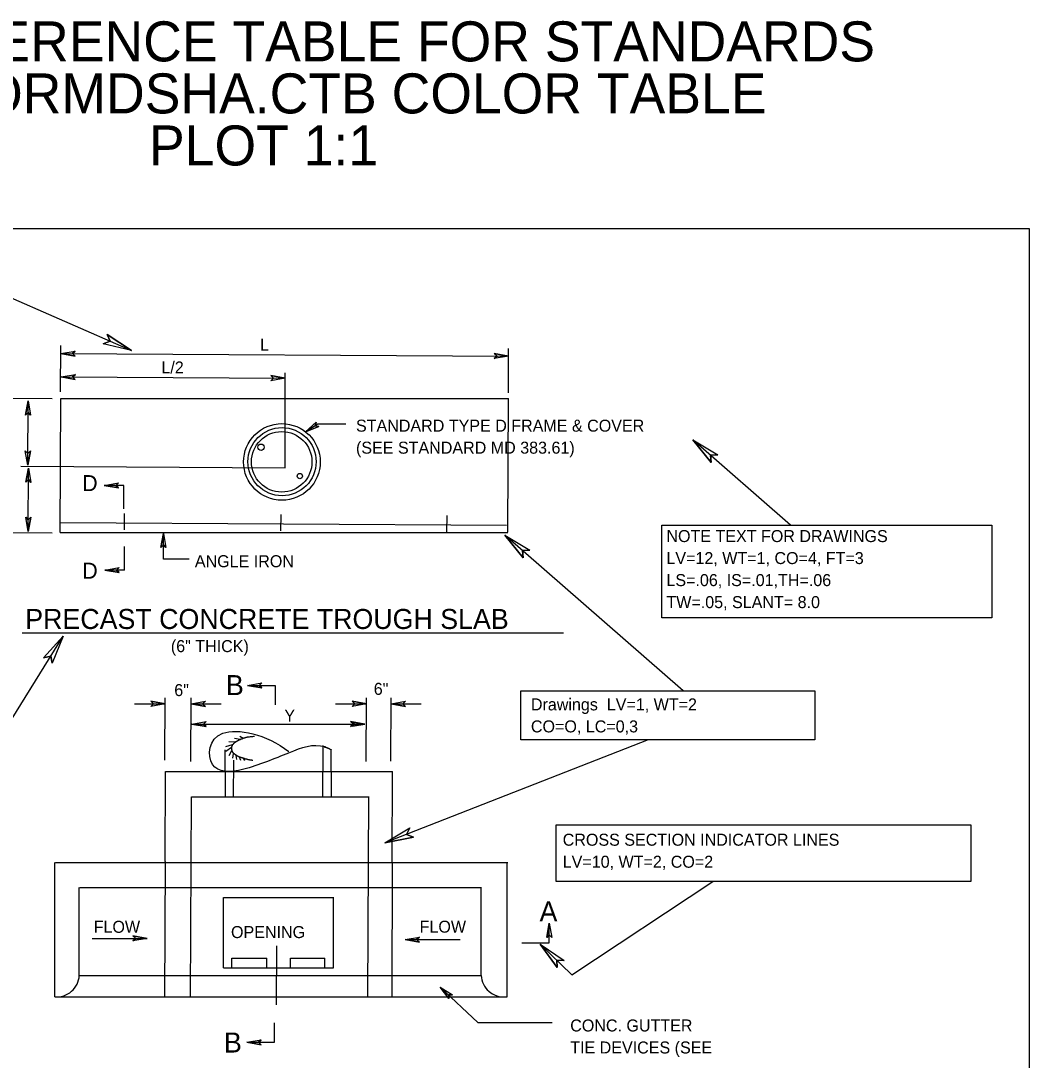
# Model space of a CAD drawing. Extents: x 0 to 1549163, y -476626 to 622136.
# Drawn here: x 2.73 to 7.77, y 12.13 to 17.33 of the extents above; entities that cross this region are included whole.
import ezdxf

# ---------------------------------------------------------------- set-up
doc = ezdxf.new("R2010")
doc.units = 0
for name, color, linetype in [('DETL-DIMS', 7, 'Continuous'), ('DETL-LINE', 7, 'Continuous'), ('DETL-NOTE', 7, 'Continuous'), ('DETL-TITL', 7, 'Continuous'), ('TTLB-TEXT', 7, 'Continuous')]:
    doc.layers.add(name, color=color, linetype=linetype)

msp = doc.modelspace()

# ---------------------------------------------------------------- linework, layer by layer
at = {"layer": 'DETL-DIMS'}
for p, q in [((2.5807, 15.9885), (3.284, 15.6805)), ((3.284, 15.6805), (3.1632, 15.7609)), ((3.1632, 15.7609), (3.1778, 15.7271)), ((2.9303, 15.4751), (2.9317, 15.7053)), ((3.1778, 15.7271), (3.143, 15.7147)), ((3.284, 15.6805), (3.143, 15.7147)), ((5.1671, 15.4696), (5.1684, 15.6913)), ((2.9318, 15.6664), (3.0034, 15.6786)), ((2.9318, 15.6664), (3.0032, 15.6534)), ((2.9318, 15.6664), (5.1682, 15.6528)), ((2.9898, 15.666), (3.0034, 15.6786)), ((3.0032, 15.6534), (2.9898, 15.666)), ((5.1102, 15.6532), (5.0966, 15.6406)), ((5.1682, 15.6528), (5.0966, 15.6406)), ((5.1682, 15.6528), (5.0968, 15.6658)), ((5.0968, 15.6658), (5.1102, 15.6532)), ((2.9324, 15.5491), (3.004, 15.5613)), ((2.9324, 15.5491), (4.0518, 15.5424)), ((2.9324, 15.5491), (3.0038, 15.5361)), ((2.9904, 15.5488), (3.004, 15.5613)), ((3.0038, 15.5361), (2.9904, 15.5488)), ((3.9938, 15.5427), (3.9802, 15.5302)), ((4.0518, 15.5424), (3.9802, 15.5302)), ((4.0518, 15.5424), (3.9804, 15.5554)), ((3.9804, 15.5554), (3.9938, 15.5427)), ((4.0522, 15.0949), (4.0522, 15.5697)), ((2.5551, 15.4426), (2.8876, 15.4406)), ((2.7681, 15.4298), (2.7551, 15.3584)), ((2.7661, 15.108), (2.7681, 15.4298)), ((2.7681, 15.4298), (2.7803, 15.3582)), ((2.7551, 15.3584), (2.7677, 15.3718)), ((2.7677, 15.3718), (2.7803, 15.3582)), ((4.1531, 15.2741), (4.2072, 15.3225)), ((4.2149, 15.3125), (4.1531, 15.2741)), ((4.1531, 15.2741), (4.2205, 15.3011)), ((4.2024, 15.3047), (4.2072, 15.3225)), ((4.2205, 15.3011), (4.2024, 15.3047)), ((4.3543, 15.3125), (4.2149, 15.3125)), ((6.0884, 15.2348), (6.1794, 15.1216)), ((6.0884, 15.2348), (6.2126, 15.1596)), ((6.5764, 14.8078), (6.0884, 15.2348)), ((2.7661, 15.108), (2.7539, 15.1796)), ((2.7665, 15.166), (2.7539, 15.1796)), ((2.7661, 15.108), (2.7791, 15.1794)), ((2.7791, 15.1794), (2.7665, 15.166)), ((6.1758, 15.1584), (6.2126, 15.1596)), ((6.1794, 15.1216), (6.1758, 15.1584)), ((2.7322, 15.103), (4.0522, 15.0949)), ((2.7699, 15.0937), (2.7568, 15.0223)), ((2.7679, 14.7766), (2.7699, 15.0937)), ((2.7699, 15.0937), (2.782, 15.0221)), ((2.7568, 15.0223), (2.7695, 15.0357)), ((2.7695, 15.0357), (2.782, 15.0221)), ((3.1479, 15.0069), (3.2194, 15.0195)), ((3.2059, 15.0069), (3.2194, 15.0195)), ((3.2467, 15.0069), (3.1479, 15.0069)), ((3.1479, 15.0069), (3.2194, 14.9943)), ((3.2194, 14.9943), (3.2059, 15.0069)), ((3.2467, 14.8895), (3.2467, 15.0069)), ((2.7679, 14.7766), (2.7558, 14.8482)), ((2.7683, 14.8346), (2.7558, 14.8482)), ((2.7679, 14.7766), (2.781, 14.848)), ((2.781, 14.848), (2.7683, 14.8346)), ((2.5591, 14.7721), (2.8879, 14.7701)), ((3.4439, 14.7673), (3.4313, 14.6958)), ((3.4439, 14.6375), (3.4439, 14.7673)), ((3.4439, 14.7673), (3.4565, 14.6958)), ((5.15, 14.7583), (5.241, 14.6451)), ((5.15, 14.7583), (5.2742, 14.6831)), ((6.0396, 13.9799), (5.15, 14.7583)), ((3.4313, 14.6958), (3.4439, 14.7093)), ((3.4439, 14.7093), (3.4565, 14.6958)), ((3.2498, 14.5836), (3.2498, 14.7011)), ((5.2374, 14.6819), (5.2742, 14.6831)), ((5.241, 14.6451), (5.2374, 14.6819)), ((3.5721, 14.6375), (3.4439, 14.6375)), ((3.151, 14.5836), (3.2225, 14.5962)), ((3.2498, 14.5836), (3.151, 14.5836)), ((3.151, 14.5836), (3.2225, 14.571)), ((3.209, 14.5836), (3.2225, 14.5962)), ((3.2225, 14.571), (3.209, 14.5836)), ((2.4408, 13.4428), (2.9424, 14.2526)), ((2.9424, 14.2526), (2.8456, 14.1444)), ((2.9424, 14.2526), (2.8886, 14.1178)), ((2.8456, 14.1444), (2.8814, 14.154)), ((2.8814, 14.154), (2.8886, 14.1178)), ((3.8637, 14.0073), (3.9352, 14.0199)), ((3.8637, 14.0073), (4.0018, 14.0073)), ((3.8637, 14.0073), (3.9352, 13.9947)), ((3.9217, 14.0073), (3.9352, 14.0199)), ((3.9352, 13.9947), (3.9217, 14.0073)), ((4.0018, 14.0073), (4.0018, 13.9411)), ((3.4526, 13.9152), (3.3811, 13.9278)), ((3.3811, 13.9278), (3.3946, 13.9152)), ((3.4513, 13.6342), (3.4527, 13.9446)), ((3.5807, 13.6263), (3.582, 13.9446)), ((3.5819, 13.9152), (3.6534, 13.9278)), ((3.6399, 13.9152), (3.6534, 13.9278)), ((4.0018, 13.9411), (4.0018, 13.9099)), ((4.4575, 13.9152), (4.386, 13.9278)), ((4.386, 13.9278), (4.3995, 13.9152)), ((4.4562, 13.6263), (4.4576, 13.9446)), ((4.5798, 13.6292), (4.5812, 13.9446)), ((4.5811, 13.9152), (4.6526, 13.9278)), ((4.6391, 13.9152), (4.6526, 13.9278)), ((3.2991, 13.9152), (3.4526, 13.9152)), ((3.4526, 13.9152), (3.3811, 13.9026)), ((3.3946, 13.9152), (3.3811, 13.9026)), ((3.5819, 13.9152), (3.732, 13.9152)), ((3.5819, 13.9152), (3.6534, 13.9026)), ((3.6534, 13.9026), (3.6399, 13.9152)), ((4.304, 13.9152), (4.4575, 13.9152)), ((4.4575, 13.9152), (4.386, 13.9026)), ((4.3995, 13.9152), (4.386, 13.9026)), ((4.5811, 13.9152), (4.6526, 13.9026)), ((4.5811, 13.9152), (4.7312, 13.9152)), ((4.6526, 13.9026), (4.6391, 13.9152)), ((3.5858, 13.8139), (3.6573, 13.8265)), ((3.6438, 13.8139), (3.6573, 13.8265)), ((4.4506, 13.8139), (4.3791, 13.8265)), ((4.3791, 13.8265), (4.3926, 13.8139)), ((4.3883, 13.8243), (4.4506, 13.8139)), ((4.3883, 13.8243), (4.3961, 13.8139)), ((3.5858, 13.8139), (4.4506, 13.8139)), ((3.5858, 13.8139), (3.6573, 13.8013)), ((3.6573, 13.8013), (3.6438, 13.8139)), ((4.4506, 13.8139), (4.3791, 13.8013)), ((4.3926, 13.8139), (4.3791, 13.8013)), ((4.3883, 13.8035), (4.4506, 13.8139)), ((4.3883, 13.8035), (4.3961, 13.8139)), ((5.8655, 13.7347), (4.5502, 13.2206)), ((4.5502, 13.2206), (4.6742, 13.2962)), ((4.5502, 13.2206), (4.6926, 13.2492)), ((4.6582, 13.2628), (4.6742, 13.2962)), ((4.6926, 13.2492), (4.6582, 13.2628)), ((5.4838, 12.5614), (6.1889, 13.0264)), ((5.3713, 12.8183), (5.3587, 12.7468)), ((5.3713, 12.7208), (5.3713, 12.8183)), ((5.3713, 12.8183), (5.3839, 12.7468)), ((3.0878, 12.7427), (3.3634, 12.7427)), ((3.3634, 12.7427), (3.2919, 12.7553)), ((3.2919, 12.7553), (3.3054, 12.7427)), ((3.3634, 12.7427), (3.2919, 12.7301)), ((3.3054, 12.7427), (3.2919, 12.7301)), ((4.6508, 12.7365), (4.7223, 12.7491)), ((4.6508, 12.7365), (4.9265, 12.7365)), ((4.6508, 12.7365), (4.7223, 12.7239)), ((4.7088, 12.7365), (4.7223, 12.7491)), ((4.7223, 12.7239), (4.7088, 12.7365)), ((5.3587, 12.7468), (5.3713, 12.7603)), ((5.3713, 12.7603), (5.3839, 12.7468)), ((5.2334, 12.7208), (5.3713, 12.7208)), ((5.3256, 12.7141), (5.4838, 12.5614)), ((5.3256, 12.7141), (5.411, 12.5967)), ((5.3256, 12.7141), (5.446, 12.6329)), ((5.411, 12.5967), (5.4091, 12.6335)), ((5.4091, 12.6335), (5.446, 12.6329)), ((5.0149, 12.3232), (4.8264, 12.4999)), ((4.8264, 12.4999), (4.8699, 12.4418)), ((4.8264, 12.4999), (4.8872, 12.4602)), ((4.8699, 12.4418), (4.8687, 12.4602)), ((4.8687, 12.4602), (4.8872, 12.4602)), ((3.9982, 12.2236), (3.9982, 12.3212)), ((5.0149, 12.3232), (5.386, 12.3232)), ((3.8602, 12.2236), (3.9317, 12.2362)), ((3.8602, 12.2236), (3.9982, 12.2236)), ((3.8602, 12.2236), (3.9317, 12.211)), ((3.9182, 12.2236), (3.9317, 12.2362)), ((3.9317, 12.211), (3.9182, 12.2236))]:
    msp.add_line(p, q, dxfattribs=at)
for points in [[(3.1632, 15.7609), (3.284, 15.6805), (3.143, 15.7147), (3.1778, 15.7271)], [(3.0032, 15.6534), (2.9318, 15.6664), (3.0034, 15.6786), (2.9898, 15.666)], [(5.0968, 15.6658), (5.1682, 15.6528), (5.0966, 15.6406), (5.1102, 15.6532)], [(3.0038, 15.5361), (2.9324, 15.5491), (3.004, 15.5613), (2.9904, 15.5488)], [(3.9804, 15.5554), (4.0518, 15.5424), (3.9802, 15.5302), (3.9938, 15.5427)], [(2.7551, 15.3584), (2.7681, 15.4298), (2.7803, 15.3582), (2.7677, 15.3718)], [(4.2205, 15.3011), (4.1531, 15.2741), (4.2072, 15.3225), (4.2024, 15.3047)], [(6.1794, 15.1216), (6.0884, 15.2348), (6.2126, 15.1596), (6.1758, 15.1584)], [(2.7791, 15.1794), (2.7661, 15.108), (2.7539, 15.1796), (2.7665, 15.166)], [(2.7568, 15.0223), (2.7699, 15.0937), (2.782, 15.0221), (2.7695, 15.0357)], [(3.2194, 14.9943), (3.1479, 15.0069), (3.2194, 15.0195), (3.2059, 15.0069)], [(2.781, 14.848), (2.7679, 14.7766), (2.7558, 14.8482), (2.7683, 14.8346)], [(3.4313, 14.6958), (3.4439, 14.7673), (3.4565, 14.6958), (3.4439, 14.7093)], [(5.241, 14.6451), (5.15, 14.7583), (5.2742, 14.6831), (5.2374, 14.6819)], [(3.2225, 14.571), (3.151, 14.5836), (3.2225, 14.5962), (3.209, 14.5836)], [(2.8456, 14.1444), (2.9424, 14.2526), (2.8886, 14.1178), (2.8814, 14.154)], [(3.9352, 13.9947), (3.8637, 14.0073), (3.9352, 14.0199), (3.9217, 14.0073)], [(3.3811, 13.9278), (3.4526, 13.9152), (3.3811, 13.9026), (3.3946, 13.9152)], [(3.6534, 13.9026), (3.5819, 13.9152), (3.6534, 13.9278), (3.6399, 13.9152)], [(4.386, 13.9278), (4.4575, 13.9152), (4.386, 13.9026), (4.3995, 13.9152)], [(4.6526, 13.9026), (4.5811, 13.9152), (4.6526, 13.9278), (4.6391, 13.9152)], [(3.6573, 13.8013), (3.5858, 13.8139), (3.6573, 13.8265), (3.6438, 13.8139)], [(4.3791, 13.8265), (4.4506, 13.8139), (4.3791, 13.8013), (4.3926, 13.8139)], [(5.4056, 13.3099), (7.4777, 13.3099), (7.4777, 13.0264), (5.4056, 13.0264)], [(4.6926, 13.2492), (4.5502, 13.2206), (4.6742, 13.2962), (4.6582, 13.2628)], [(5.3587, 12.7468), (5.3713, 12.8183), (5.3839, 12.7468), (5.3713, 12.7603)], [(3.2919, 12.7553), (3.3634, 12.7427), (3.2919, 12.7301), (3.3054, 12.7427)], [(4.7223, 12.7239), (4.6508, 12.7365), (4.7223, 12.7491), (4.7088, 12.7365)], [(5.411, 12.5967), (5.3256, 12.7141), (5.446, 12.6329), (5.4091, 12.6335)], [(4.8699, 12.4418), (4.8264, 12.4999), (4.8872, 12.4602), (4.8687, 12.4602)], [(3.9317, 12.211), (3.8602, 12.2236), (3.9317, 12.2362), (3.9182, 12.2236)]]:
    msp.add_lwpolyline(points, close=True, dxfattribs=at)
at = {"layer": 'DETL-LINE'}
for p, q in [((2.928, 14.7716), (2.932, 15.4408)), ((2.932, 15.4408), (5.1683, 15.4408)), ((5.1643, 14.7737), (5.1683, 15.4408)), ((3.2489, 14.7849), (3.2494, 14.867)), ((4.0308, 14.7801), (4.0313, 14.8622)), ((2.9297, 14.8212), (5.1569, 14.8077)), ((4.8602, 14.775), (4.8607, 14.8571)), ((2.928, 14.7716), (5.1643, 14.7716)), ((3.8032, 13.7234), (3.7711, 13.7258)), ((3.8275, 13.7363), (3.7995, 13.7426)), ((3.843, 13.7426), (3.8256, 13.7513)), ((3.7523, 13.5744), (3.7527, 13.6857)), ((3.7878, 13.7097), (3.7543, 13.6998)), ((3.7834, 13.6961), (3.7555, 13.6762)), ((3.7847, 13.6806), (3.7711, 13.6551)), ((3.7921, 13.6663), (3.7884, 13.644)), ((4.2409, 13.4477), (4.2419, 13.7062)), ((4.2818, 13.5734), (4.2823, 13.6841)), ((3.7942, 13.4497), (3.795, 13.6336)), ((3.8052, 13.6576), (3.8089, 13.6371)), ((3.8218, 13.6502), (3.8293, 13.6334)), ((3.8398, 13.6445), (3.8485, 13.6315)), ((3.4522, 13.1271), (3.454, 13.577)), ((3.454, 13.577), (4.5889, 13.577)), ((3.7523, 13.5744), (3.7523, 13.4517)), ((4.2818, 13.5734), (4.2812, 13.4497)), ((4.5869, 13.1236), (4.5889, 13.577)), ((3.5789, 12.4513), (3.5833, 13.4502)), ((3.5833, 13.4502), (4.4691, 13.4502)), ((4.4649, 12.4538), (4.4691, 13.4521)), ((2.9011, 12.4507), (2.9011, 13.1228)), ((2.904, 13.1228), (5.1643, 13.1228)), ((3.4522, 13.1271), (3.4492, 12.4507)), ((4.5869, 13.1236), (4.584, 12.4519)), ((5.1613, 12.4507), (5.1613, 13.1228)), ((3.0238, 12.5573), (3.0238, 12.9964)), ((3.0257, 12.9964), (5.0326, 12.9964)), ((5.0306, 12.5573), (5.0306, 12.9964)), ((3.7432, 12.5961), (3.7432, 12.9478)), ((3.7448, 12.9478), (4.2957, 12.9478)), ((4.2942, 12.5961), (4.2942, 12.9478)), ((4.0086, 12.4107), (4.0099, 12.7063)), ((3.7851, 12.5961), (3.7853, 12.6437)), ((3.7853, 12.6437), (3.9609, 12.6437)), ((3.9606, 12.5961), (3.9609, 12.6437)), ((4.0791, 12.5961), (4.0793, 12.6437)), ((4.0793, 12.6437), (4.2498, 12.6437)), ((4.2496, 12.5961), (4.2498, 12.6437)), ((3.7432, 12.5961), (4.2942, 12.5961)), ((3.0238, 12.5573), (5.0306, 12.5573)), ((2.9011, 12.4507), (5.1613, 12.4507))]:
    msp.add_line(p, q, dxfattribs=at)
msp.add_lwpolyline([(5.2291, 13.9799), (6.6982, 13.9799), (6.6982, 13.7347), (5.2291, 13.7347)], close=True, dxfattribs=at)
for centre, major_axis in [((4.0358, 15.1241), (0.1914, 0)), ((4.0364, 15.1254), (0.1702, 0)), ((4.0349, 15.1247), (0.1511, 0)), ((3.9314, 15.1978), (0.0159, 0)), ((4.1254, 15.0535), (0.0134, 0))]:
    msp.add_ellipse(centre, major_axis=major_axis, ratio=0.999935, dxfattribs=at)
for centre, major_axis, start_param, end_param in [((2.9101, 12.5643), (0.1139, 0), 4.632879, 6.222037), ((5.1444, 12.5643), (-0.1139, 0), 0.061149, 1.650306)]:
    msp.add_ellipse(centre, major_axis=major_axis, ratio=0.999935, start_param=start_param, end_param=end_param, dxfattribs=at)
msp.add_open_spline([(4.2531, 13.6997), (4.187, 13.716), (4.0846, 13.6776), (3.8323, 13.5707), (3.6584, 13.5698), (3.6713, 13.8264), (3.9573, 13.7643), (4.07, 13.6769)], degree=3, dxfattribs=at)
for points in [[(3.8981, 13.7513), (3.8944, 13.7513), (3.8827, 13.75), (3.8721, 13.7494), (3.8653, 13.7488), (3.8634, 13.7488), (3.8627, 13.7481), (3.8597, 13.7476), (3.8585, 13.7476), (3.8572, 13.7469), (3.856, 13.7469), (3.8553, 13.7463), (3.8548, 13.7463), (3.8535, 13.7457), (3.8529, 13.7457), (3.851, 13.7451), (3.8498, 13.7444), (3.8492, 13.7444), (3.8467, 13.7438), (3.8461, 13.7432), (3.8448, 13.7432), (3.8436, 13.7426), (3.843, 13.742), (3.8418, 13.742), (3.8393, 13.7407), (3.8374, 13.7401), (3.8367, 13.7394), (3.8343, 13.7388), (3.8336, 13.7388), (3.8319, 13.7383), (3.8305, 13.7376), (3.8299, 13.737), (3.8268, 13.7357), (3.8262, 13.7351), (3.825, 13.7351), (3.8237, 13.7346), (3.8231, 13.7339), (3.8225, 13.7339), (3.8188, 13.732), (3.8181, 13.7313), (3.8176, 13.7313), (3.8163, 13.7309), (3.8157, 13.7302), (3.8144, 13.7295), (3.8126, 13.7283), (3.8114, 13.7283), (3.8101, 13.7271), (3.8094, 13.7271), (3.8089, 13.7264), (3.8076, 13.7258), (3.807, 13.7252), (3.8057, 13.7252), (3.8039, 13.7234), (3.802, 13.7221), (3.8014, 13.7215), (3.8002, 13.7209), (3.7995, 13.7209), (3.7977, 13.719), (3.7964, 13.7184), (3.7958, 13.7178), (3.7946, 13.7159), (3.794, 13.7153), (3.7927, 13.7147), (3.7921, 13.7141), (3.7921, 13.7134), (3.7909, 13.7122), (3.7909, 13.7116), (3.789, 13.7097), (3.7878, 13.7072), (3.7878, 13.7066), (3.7865, 13.706), (3.7859, 13.7048), (3.7859, 13.7042), (3.7853, 13.7035), (3.7853, 13.7022), (3.7847, 13.701), (3.7841, 13.6991), (3.7841, 13.6979), (3.7847, 13.6892), (3.7847, 13.6862), (3.7853, 13.6855), (3.7853, 13.6837), (3.7859, 13.683), (3.7859, 13.6824), (3.7859, 13.6812), (3.7859, 13.6806), (3.7865, 13.6793), (3.7871, 13.6786), (3.7871, 13.6769), (3.7878, 13.6762), (3.7878, 13.6756), (3.7884, 13.6749), (3.789, 13.6738), (3.7915, 13.6712), (3.7921, 13.67), (3.7927, 13.6694), (3.7933, 13.6694)], [(3.7933, 13.6694), (3.7952, 13.6675), (3.7958, 13.6675), (3.7983, 13.665), (3.7995, 13.6644), (3.8008, 13.6632), (3.802, 13.6626), (3.8026, 13.6619), (3.8032, 13.6619), (3.8046, 13.6607), (3.8052, 13.6607), (3.8057, 13.6601), (3.807, 13.6595), (3.8076, 13.6589), (3.8089, 13.6582), (3.8089, 13.6576), (3.8094, 13.6576), (3.8101, 13.657), (3.8114, 13.6564), (3.8126, 13.6551), (3.8144, 13.6545), (3.8157, 13.6539), (3.8163, 13.6539), (3.8188, 13.6527), (3.82, 13.652), (3.8206, 13.652), (3.8218, 13.6514), (3.8225, 13.6508), (3.8231, 13.6508), (3.8244, 13.6502), (3.8262, 13.6502), (3.8262, 13.6496), (3.8268, 13.6496), (3.8281, 13.649), (3.8293, 13.649), (3.8299, 13.6483), (3.8305, 13.6483), (3.8319, 13.6477), (3.833, 13.6477), (3.8343, 13.6471), (3.8356, 13.6471), (3.8361, 13.6465), (3.8367, 13.6465), (3.8381, 13.6458), (3.8393, 13.6458), (3.8398, 13.6452), (3.8411, 13.6445), (3.843, 13.6445), (3.8436, 13.644), (3.8442, 13.644), (3.8448, 13.6434), (3.8467, 13.6434), (3.8479, 13.6428), (3.8485, 13.6428), (3.8492, 13.6421), (3.8504, 13.6421), (3.851, 13.6414), (3.8523, 13.6414), (3.8523, 13.6408), (3.8548, 13.6403), (3.8572, 13.6403), (3.8579, 13.6397), (3.8585, 13.6397), (3.8597, 13.6397), (3.8603, 13.6391), (3.8616, 13.6391), (3.8623, 13.6384), (3.8634, 13.6384), (3.8647, 13.6377), (3.8671, 13.6377), (3.8678, 13.6371), (3.869, 13.6371), (3.8697, 13.6371), (3.8708, 13.6366), (3.8721, 13.6366), (3.8739, 13.636), (3.8752, 13.636), (3.8777, 13.6353), (3.8808, 13.6353), (3.8814, 13.6347), (3.8832, 13.6347), (3.8852, 13.6347), (3.8864, 13.634), (3.8913, 13.634)], [(4.246, 13.7005), (4.2473, 13.7005), (4.2486, 13.6998), (4.2504, 13.6998), (4.2504, 13.6991), (4.2523, 13.6991), (4.2523, 13.6985), (4.2535, 13.6985), (4.2547, 13.6979), (4.256, 13.6979), (4.2566, 13.6973), (4.2584, 13.6973), (4.2591, 13.6967), (4.2604, 13.6967), (4.2609, 13.6961), (4.2616, 13.6961), (4.2622, 13.6954), (4.2641, 13.6954), (4.2646, 13.6948), (4.2653, 13.6948), (4.2659, 13.6942), (4.2665, 13.6942), (4.2678, 13.6936), (4.2684, 13.6936), (4.2684, 13.693), (4.2696, 13.693), (4.2696, 13.6923), (4.2709, 13.6923), (4.2715, 13.6917), (4.2721, 13.6917), (4.2733, 13.6904), (4.274, 13.6904), (4.274, 13.6899), (4.2747, 13.6899), (4.2752, 13.6899), (4.2752, 13.6892), (4.2764, 13.6892), (4.2764, 13.6886), (4.2771, 13.6886), (4.2771, 13.688), (4.2784, 13.688), (4.2784, 13.6874), (4.2789, 13.6874), (4.2802, 13.6862), (4.2808, 13.6862), (4.2814, 13.6862), (4.2814, 13.6855), (4.2821, 13.6855), (4.2827, 13.6849)]]:
    msp.add_spline(points, degree=3, dxfattribs=at)
at = {"layer": 'DETL-NOTE'}
msp.add_lwpolyline([(5.9329, 14.8078), (7.5815, 14.8078), (7.5815, 14.3446), (5.9329, 14.3446)], close=True, dxfattribs=at)
at = {"layer": 'DETL-TITL'}
msp.add_line((2.7389, 14.2707), (5.4429, 14.2707), dxfattribs=at)
at = {"layer": 'TTLB-TEXT'}
msp.add_lwpolyline([(0.3943, 16.2906), (7.7685, 16.2906), (7.7685, 5.9375), (0.3943, 5.9375)], close=True, dxfattribs=at)

# ---------------------------------------------------------------- texts
at = {"layer": 'DETL-DIMS'}
for s, p in [('CROSS SECTION INDICATOR LINES', (5.4384, 13.206)), ('LV=10, WT=2, CO=2 ', (5.4384, 13.096))]:
    msp.add_text(s, height=0.06, dxfattribs=at).set_placement(p)
at = {"layer": 'DETL-LINE'}
for s, height, p in [('SAMPLE PREFERENCE TABLE FOR STANDARDS', 0.2, (0.727, 17.126)), ('ATTACH CLORMDSHA.CTB COLOR TABLE', 0.2, (1.0473, 16.866)), ('PLOT 1:1', 0.2, (3.3719, 16.606)), ('Drawings  LV=1, WT=2', 0.06, (5.2795, 13.8823)), ('CO=O, LC=0,3', 0.06, (5.2795, 13.7723))]:
    msp.add_text(s, height=height, dxfattribs=at).set_placement(p)
at = {"layer": 'DETL-NOTE'}
for s, height, p in [('L', 0.06, (3.9267, 15.6803)), ('L/2', 0.06, (3.4338, 15.5664)), ('STANDARD TYPE D FRAME & COVER', 0.06, (4.4058, 15.2754)), ('(SEE STANDARD MD 383.61)', 0.06, (4.4058, 15.1654)), ('NOTE TEXT FOR DRAWINGS', 0.06, (5.9564, 14.7236)), ('ANGLE IRON', 0.06, (3.6009, 14.598)), ('LV=12, WT=1, CO=4, FT=3', 0.06, (5.9564, 14.6136)), ('LS=.06, IS=.01,TH=.06', 0.06, (5.9564, 14.5036)), ('TW=.05, SLANT= 8.0', 0.06, (5.9564, 14.3936)), ('(6" THICK)', 0.06, (3.481, 14.1736)), ('B', 0.1, (3.7561, 13.9588)), ('6"', 0.06, (3.4981, 13.954)), ('6"', 0.06, (4.4946, 13.9601)), ('Y', 0.06, (4.0479, 13.8265)), ('FLOW', 0.06, (3.0956, 12.7707)), ('FLOW', 0.06, (4.7237, 12.7714)), ('OPENING', 0.06, (3.7815, 12.7444)), ('CONC. GUTTER', 0.06, (5.4759, 12.2776)), ('TIE DEVICES (SEE', 0.06, (5.4759, 12.1676))]:
    msp.add_text(s, height=height, dxfattribs=at).set_placement(p)
at = {"layer": 'DETL-TITL'}
for s, height, p in [('D', 0.08, (3.038, 14.9783)), ('D', 0.08, (3.0384, 14.5406)), ('PRECAST CONCRETE TROUGH SLAB', 0.1, (2.7538, 14.2893)), ('A', 0.1, (5.3226, 12.8278)), ('B', 0.1, (3.7463, 12.1724))]:
    msp.add_text(s, height=height, dxfattribs=at).set_placement(p)

doc.saveas('drawing.dxf')
